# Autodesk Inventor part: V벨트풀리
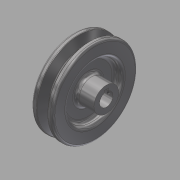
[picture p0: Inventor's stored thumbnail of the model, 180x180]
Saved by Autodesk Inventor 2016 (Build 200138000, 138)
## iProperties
Created: 2015-11
Part Number: V벨트풀리
Material: 강철, 탄소
Document SubType Name: Modeling
Designer: mduedu
Density: 1 g/cm^3
Appearance: 반광택
Author: mduedu
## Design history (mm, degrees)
sketch "스케치1"
  geometry: L1 (-9.5, 0)-(9.5, 0); L2 (0, 0)-(0, 37.7); L3 (-4.825, 37.7)-(-9.5, 37.7); L4 (-9.5, 37.7)-(-9.5, 0); L5 (0, 28.7)-(-2.074, 28.7); L6 (-2.074, 28.7)-(-4.825, 37.7); L7 (4.825, 37.7)-(9.5, 37.7); L8 (9.5, 37.7)-(9.5, 0); L9 (0, 28.7)-(2.074, 28.7); L10 (2.074, 28.7)-(4.825, 37.7); L11 (-9.5, 35)-(9.5, 35); 3 further points
  constraints: 22 end point, 7 point on line, 4 perpendicular, 3 symmetric about line, 1 coincident, 1 horizontal, 1 horizontal alignment, 1 midpoint, 1 vertical
  dimensions: "d0" = 19 distance of L1.start L1.end; "d2" = 75.4 diameter of L2.end L1 (derived); "d3" = 34 deg angle of L10 L6; "d4" = 6.3 distance between parallel lines of L11 L9; "d5" = 2.7 distance between parallel lines of L7 L11; "d6" = 8 distance of point (4, 35) point (-4, 35); "d7" = 70 diameter of L11 L1
revolve "회전1" sketch "스케치1" stored, may be unused: angle "d8" = 90 deg
sketch "스케치2"
  geometry: C1 r 24 at (0, 0); C2 r 11 at (0, 0); 1 further point
  constraints: 2 centre point, 2 coincident
  dimensions: "d9" = 48 diameter of C1; "d10" = 22 diameter of C2
extrude "돌출1" cut sketch "스케치2" distance "d11" = 6; taper "d12" = 0 deg
extrude "돌출3" join sketch "스케치2" distance "d37" = 10; taper "d38" = 0 deg
fillet "모깎기1" dims "d13" = 3
fillet "모깎기2" dims "d14" = 3
fillet "모깎기3" dims "d15" = 1, "d16" = 0.5, "d17" = 2
hole "구멍1" diameter "d20" = 12; stored, may be unused: countersink angle "d24" = 90 deg, drill point angle "d26" = 118 deg; dims "d21" = 6, "d22" = 4, "d23" = 2, "d25" = 8, "d39" = 10, "d40" = 10
sketch "스케치3"
  geometry: L1 (-2, 0)-(2, 0); L2 (2, 0)-(2, 7.8); L3 (2, 7.8)-(-2, 7.8); L4 (-2, 7.8)-(-2, 0); 2 further points
  constraints: 8 end point, 2 parallel, 1 coincident, 1 horizontal, 1 midpoint, 1 perpendicular
  dimensions: "d27" = 4 distance of L2.end L3.end; "d29" = 7.8 distance of L3.end L1.start
extrude "돌출2" cut sketch "스케치3" stored distance "d30" = 6; taper "d31" = 0 deg
chamfer "모따기1" distance "d32" = 0.5; stored, may be unused: second distance "d33" = 2, angle "d34" = 45 deg
node "작업 평면1"
sketch "스케치4"
  geometry: L1 (-19, 11)-(-19, -11) reference; 2 further points
  constraints: 1 horizontal alignment
  dimensions: "d41" = 25 distance from line of point (6, 0) L1
hole "구멍2" sketch "스케치4" at (6, 0) diameter "d42" = 2.459; stored, may be unused: countersink angle "d46" = 90 deg, drill point angle "d48" = 118 deg; dims "d43" = 6, "d44" = 4, "d45" = 2, "d47" = 8
node "솔리드1"
mirror "대칭1"
